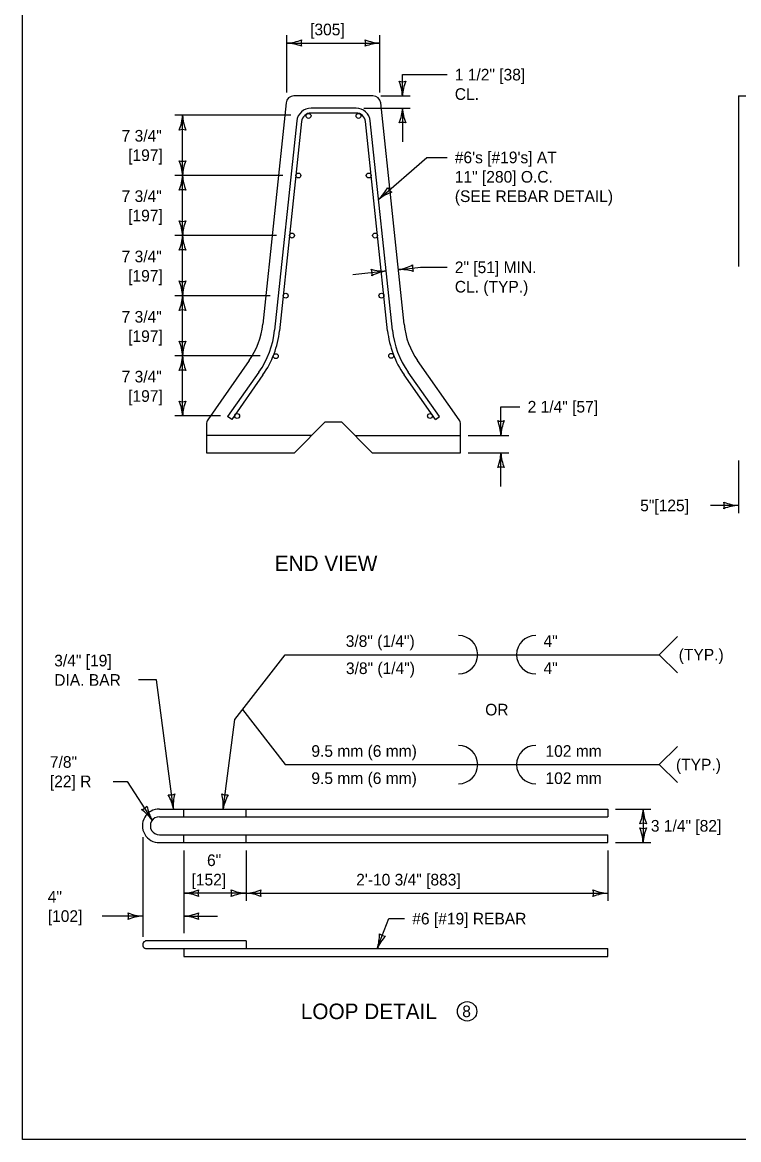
# Model space of a CAD drawing. Extents: x 49991.4 to 50021, y 49987.6 to 50011.4.
# Drawn here: x 49999.38 to 50003.08, y 49987.8 to 49993.56 of the extents above; entities that cross this region are included whole.
import ezdxf

# ---------------------------------------------------------------- set-up
doc = ezdxf.new("R2010")
doc.units = 0
for name, color, linetype in [('Level 1', 7, 'Continuous'), ('Level 2', 7, 'Continuous'), ('Level 3', 7, 'Continuous'), ('Level 4', 7, 'Continuous')]:
    doc.layers.add(name, color=color, linetype=linetype)

msp = doc.modelspace()

# ---------------------------------------------------------------- linework, layer by layer
at = {"layer": 'Level 1'}
for p, q in [((50001.1913, 49993.1797), (50000.7833, 49993.1797)), ((50003.0765, 49993.1796), (50007.8063, 49993.1796)), ((50003.0765, 49993.1796), (50003.0766, 49992.2998)), ((50000.7435, 49993.1439), (50000.6231, 49992.0024)), ((50001.1038, 49993.1169), (50000.8721, 49993.1169)), ((50001.3515, 49992.0024), (50001.2311, 49993.1439)), ((50000.7983, 49993.0507), (50000.6842, 49991.972)), ((50000.8235, 49993.0481), (50000.7094, 49991.9694)), ((50001.1038, 49993.0918), (50000.8721, 49993.0918)), ((50001.2666, 49991.9694), (50001.1525, 49993.0481)), ((50001.2917, 49991.972), (50001.1776, 49993.0507)), ((50000.553, 49991.815), (50000.3395, 49991.51)), ((50001.6351, 49991.51), (50001.4216, 49991.815)), ((50000.6032, 49991.7559), (50000.442, 49991.5263)), ((50000.6239, 49991.7415), (50000.4627, 49991.5118)), ((50001.5133, 49991.5118), (50001.3521, 49991.7415)), ((50001.534, 49991.5263), (50001.3728, 49991.7559)), ((50000.3323, 49991.4871), (50000.3323, 49991.3397)), ((50000.4627, 49991.5118), (50000.442, 49991.5263)), ((50000.9448, 49991.4997), (50000.7873, 49991.3397)), ((50000.9448, 49991.4997), (50001.0298, 49991.4997)), ((50001.0298, 49991.4997), (50001.1873, 49991.3397)), ((50001.5133, 49991.5118), (50001.534, 49991.5263)), ((50001.6423, 49991.3397), (50001.6423, 49991.4871)), ((50000.3323, 49991.3397), (50000.7873, 49991.3397)), ((50001.1873, 49991.3397), (50001.6423, 49991.3397)), ((50000.0909, 49989.5035), (50002.4015, 49989.5035)), ((50000.5367, 49989.4634), (50000.5367, 49989.5035)), ((50002.4015, 49989.5035), (50002.4015, 49989.4634)), ((50000.0908, 49989.4634), (50002.4015, 49989.4634)), ((50000.0908, 49989.3705), (50002.4015, 49989.3705)), ((50000.5367, 49989.3303), (50000.5367, 49989.3705)), ((50002.4015, 49989.3303), (50002.4015, 49989.3705)), ((50000.0908, 49989.3303), (50000.5367, 49989.3303)), ((50000.2156, 49989.3303), (50002.4015, 49989.3303)), ((50000.2156, 49989.3303), (50000.2156, 49989.3303)), ((50000.5367, 49989.3303), (50000.5367, 49989.3303)), ((50002.4015, 49989.3303), (50002.4015, 49989.3303)), ((50000.5367, 49988.8237), (50000.0243, 49988.8237)), ((50000.0243, 49988.7836), (50002.4015, 49988.7836)), ((50000.2156, 49988.7836), (50000.2156, 49988.7435)), ((50000.5367, 49988.8237), (50000.5367, 49988.7836)), ((50002.4015, 49988.7435), (50002.4015, 49988.7836)), ((50000.2156, 49988.7435), (50002.4015, 49988.7435))]:
    msp.add_line(p, q, dxfattribs=at)
msp.add_lwpolyline([(49999.3835, 49998.9992), (50016.7501, 49998.9992), (50016.7501, 49987.7988), (49999.3835, 49987.7988)], close=True, dxfattribs=at)
for centre, radius, start, end in [((50000.089, 49989.4169), 0.0866, 88.75473, 271.19725), ((50000.0899, 49989.417), 0.0465, 88.88791, 271.11208), ((50000.0243, 49988.8037), 0.0201, 89.93569, 270.06431)]:
    msp.add_arc(centre, radius, start, end, dxfattribs=at)
for centre, major_axis, ratio, start_param, end_param in [((50000.7833, 49993.1397), (-0.04, 0), 0.999982, 4.712389, 6.178105), ((50001.1913, 49993.1397), (-0.04, 0), 0.999982, 3.246673, 4.712389), ((50000.8721, 49993.0429), (-0.0742, 0), 0.997211, 4.712389, 6.178105), ((50001.1038, 49993.0429), (0.0742, 0), 0.997211, 0.10508, 1.570796), ((50000.8721, 49993.0429), (-0.049, 0), 0.997211, 4.712389, 6.178105), ((50001.1038, 49993.0429), (-0.049, 0), 0.997211, 3.246673, 4.712389), ((50000.2253, 49992.0444), (0.4, 0), 0.999982, 5.672459, 6.178105), ((50000.2243, 49992.0204), (0.4625, 0), 0.997211, 5.672459, 6.178105), ((50000.2243, 49992.0204), (0.4877, 0), 0.997211, 5.672459, 6.178105), ((50001.7517, 49992.0204), (-0.4877, 0), 0.997211, 0.10508, 0.610726), ((50001.7517, 49992.0204), (-0.4625, 0), 0.997211, 0.10508, 0.610726), ((50001.7492, 49992.0444), (-0.4, 0), 0.999982, 0.10508, 0.610726), ((50000.3723, 49991.4871), (-0.04, 0), 0.999982, 5.672459, 6.283185), ((50001.6023, 49991.4871), (0.04, 0), 0.999982, 0, 0.610726)]:
    msp.add_ellipse(centre, major_axis=major_axis, ratio=ratio, start_param=start_param, end_param=end_param, dxfattribs=at)
for centre in [(50000.8592, 49993.0768), (50001.1167, 49993.0768), (50000.8067, 49992.7699), (50001.1693, 49992.7699), (50000.7739, 49992.4599), (50001.202, 49992.46), (50000.7411, 49992.1498), (50001.2348, 49992.15), (50000.6901, 49991.8381), (50001.2852, 49991.8399), (50000.4907, 49991.5299), (50001.4852, 49991.5299)]:
    msp.add_ellipse(centre, major_axis=(0.0126, 0), ratio=0.999982, dxfattribs=at)
at = {"layer": 'Level 2'}
msp.add_circle((50001.6766, 49988.4603), 0.05, dxfattribs=at)
at = {"layer": 'Level 3'}
for p, q in [((50000.7473, 49993.1971), (50000.7473, 49993.4925)), ((50000.7473, 49993.4525), (50001.2273, 49993.4525)), ((50001.2273, 49993.1971), (50001.2273, 49993.4925)), ((50001.3432, 49993.1797), (50001.3432, 49993.2896)), ((50001.3432, 49993.2896), (50001.5731, 49993.2896)), ((50001.2313, 49993.1797), (50001.3832, 49993.1797)), ((50001.1438, 49993.1169), (50001.3832, 49993.1169)), ((50001.3432, 49993.1169), (50001.3432, 49992.9435)), ((50000.7679, 49993.0799), (50000.1695, 49993.0799)), ((50000.2095, 49992.7689), (50000.2095, 49993.0799)), ((50001.2205, 49992.6459), (50001.469, 49992.8629)), ((50001.469, 49992.8629), (50001.5731, 49992.8629)), ((50000.7267, 49992.7699), (50000.1695, 49992.7699)), ((50000.2095, 49992.4578), (50000.2095, 49992.7689)), ((50000.6939, 49992.4599), (50000.1695, 49992.4599)), ((50000.2095, 49992.1468), (50000.2095, 49992.4578)), ((50001.3217, 49992.2841), (50001.4371, 49992.2963)), ((50001.4371, 49992.2963), (50001.5731, 49992.2963)), ((50001.0869, 49992.2594), (50001.2594, 49992.2776)), ((50000.6611, 49992.1498), (50000.1695, 49992.1499)), ((50000.2095, 49991.8357), (50000.2095, 49992.1468)), ((50000.61, 49991.8399), (50000.1695, 49991.8399)), ((50000.2095, 49991.5299), (50000.2095, 49991.8357)), ((50001.851, 49991.5774), (50001.9487, 49991.5774)), ((50001.851, 49991.4297), (50001.851, 49991.5774)), ((50000.4046, 49991.5299), (50000.1695, 49991.5299)), ((50001.6823, 49991.4297), (50001.891, 49991.4297)), ((50001.6823, 49991.3397), (50001.891, 49991.3397)), ((50001.851, 49991.1662), (50001.851, 49991.3397)), ((50003.0765, 49991.2997), (50003.0765, 49991.0287)), ((50003.0765, 49991.0687), (50002.9318, 49991.0687)), ((50002.6675, 49990.2992), (50002.7609, 49990.3926)), ((50000.4785, 49989.9647), (50000.7378, 49990.2992)), ((50000.7378, 49990.2992), (50002.6675, 49990.2992)), ((50002.6675, 49990.2992), (50002.7609, 49990.206)), ((50000.0755, 49990.1688), (49999.9828, 49990.1688)), ((50000.5182, 49990.0158), (50000.7378, 49989.7325)), ((50002.6671, 49989.7325), (50002.7605, 49989.8259)), ((50000.7378, 49989.7325), (50002.6671, 49989.7325)), ((50002.6671, 49989.7325), (50002.7605, 49989.6393)), ((49999.8522, 49989.6459), (49999.9233, 49989.6459)), ((49999.9233, 49989.6459), (50000.0531, 49989.4454)), ((50002.4415, 49989.5035), (50002.624, 49989.5035)), ((50002.584, 49989.5035), (50002.584, 49989.3303)), ((50000.0043, 49989.3588), (50000.0043, 49988.8437)), ((50002.4415, 49989.3303), (50002.624, 49989.3303)), ((50000.2156, 49989.2903), (50000.2156, 49988.8637)), ((50000.5367, 49989.2903), (50000.5367, 49989.0293)), ((50002.4014, 49989.2903), (50002.4014, 49989.0293)), ((50000.5367, 49989.0693), (50000.2156, 49989.0693)), ((50000.5367, 49989.0693), (50002.4014, 49989.0693)), ((50000.0043, 49988.9514), (49999.795, 49988.9514)), ((50000.2156, 49988.9514), (50000.3891, 49988.9514)), ((50001.2729, 49988.9383), (50001.3538, 49988.9383))]:
    msp.add_line(p, q, dxfattribs=at)
for points in [[(50000.1622, 49989.5035), (50000.0755, 49990.1688)], [(50000.4184, 49989.5035), (50000.4785, 49989.9647)], [(50001.2131, 49988.7836), (50001.2729, 49988.9383)]]:
    msp.add_lwpolyline(points, dxfattribs=at)
for centre, radius, start, end in [((50000.7358, 49993.6852), 0.233, 272.82731, 292.07716), ((50000.7381, 49993.2303), 0.2223, 67.45601, 87.63952), ((50000.8755, 49993.4525), 0.0548, 162.13882, 197.86118), ((50001.2364, 49993.6746), 0.2223, 247.45601, 267.63952), ((50001.0991, 49993.4525), 0.0548, 342.13882, 17.86118), ((50001.2388, 49993.2198), 0.233, 92.82731, 112.07716), ((50001.3432, 49993.3079), 0.0548, 252.13882, 287.86118), ((50001.1105, 49993.1682), 0.233, 2.82731, 22.07716), ((50001.5653, 49993.1705), 0.2223, 157.45601, 177.63952), ((50001.1211, 49993.1261), 0.2223, 337.45601, 357.63952), ((50001.5759, 49993.1284), 0.233, 182.82731, 202.07716), ((49999.9874, 49993.0891), 0.2223, 337.45601, 357.63952), ((50000.4422, 49993.0914), 0.233, 182.82731, 202.07716), ((50001.3432, 49992.9887), 0.0548, 72.13882, 107.86118), ((50000.2095, 49992.9517), 0.0548, 72.13882, 107.86118), ((50000.2095, 49992.8981), 0.0548, 252.13882, 287.86118), ((49999.9768, 49992.7584), 0.233, 2.82731, 22.07716), ((50000.4316, 49992.7608), 0.2223, 157.45601, 177.63952), ((49999.9874, 49992.7791), 0.2223, 337.45601, 357.63952), ((50000.4422, 49992.7814), 0.233, 182.82731, 202.07716), ((50000.2095, 49992.6417), 0.0548, 72.13882, 107.86118), ((50001.0587, 49992.8136), 0.233, 313.95136, 333.20121), ((50001.317, 49992.7302), 0.0548, 203.26286, 238.98523), ((50001.3597, 49992.4725), 0.2223, 108.58006, 128.76356), ((50000.2095, 49992.5881), 0.0548, 252.13882, 287.86118), ((49999.9768, 49992.4484), 0.233, 2.82731, 22.07716), ((50000.4316, 49992.4508), 0.2223, 157.45601, 177.63952), ((49999.9874, 49992.4691), 0.2223, 337.45601, 357.63952), ((50000.4422, 49992.4714), 0.233, 182.82731, 202.07716), ((50000.2095, 49992.3317), 0.0548, 72.13882, 107.86118), ((50001.2859, 49992.5144), 0.233, 278.84787, 298.09772), ((50001.4492, 49992.2976), 0.0548, 168.15938, 203.88174), ((50001.2452, 49992.4994), 0.2223, 253.47657, 273.66008), ((50001.1319, 49992.2641), 0.0548, 348.15938, 23.88174), ((50001.2952, 49992.0473), 0.233, 98.84787, 118.09772), ((50001.3359, 49992.0623), 0.2223, 73.47657, 93.66008), ((50000.2095, 49992.2781), 0.0548, 252.13882, 287.86118), ((49999.9768, 49992.1384), 0.233, 2.82731, 22.07716), ((50000.4316, 49992.1408), 0.2223, 157.45601, 177.63952), ((49999.9874, 49992.1591), 0.2223, 337.45601, 357.63952), ((50000.4422, 49992.1614), 0.233, 182.82731, 202.07716), ((50000.2095, 49992.0217), 0.0548, 72.13882, 107.86118), ((50000.2095, 49991.9681), 0.0548, 252.13882, 287.86118), ((49999.9768, 49991.8284), 0.233, 2.82731, 22.07716), ((50000.4316, 49991.8308), 0.2223, 157.45601, 177.63952), ((49999.9874, 49991.8491), 0.2223, 337.45601, 357.63952), ((50000.4422, 49991.8514), 0.233, 182.82731, 202.07716), ((50000.2095, 49991.7117), 0.0548, 72.13882, 107.86118), ((50000.2095, 49991.6581), 0.0548, 252.13882, 287.86118), ((49999.9768, 49991.5184), 0.233, 2.82731, 22.07716), ((50000.4316, 49991.5208), 0.2223, 157.45601, 177.63952), ((50001.851, 49991.5579), 0.0548, 252.13882, 287.86118), ((50001.6183, 49991.4182), 0.233, 2.82731, 22.07716), ((50002.0731, 49991.4205), 0.2223, 157.45601, 177.63952), ((50001.6289, 49991.3488), 0.2223, 337.45601, 357.63952), ((50002.0837, 49991.3512), 0.233, 182.82731, 202.07716), ((50001.851, 49991.2115), 0.0548, 72.13882, 107.86118), ((50003.0857, 49991.2909), 0.2223, 247.45601, 267.63952), ((50002.9483, 49991.0687), 0.0548, 342.13882, 17.86118), ((50003.088, 49990.836), 0.233, 92.82731, 112.07716), ((50001.6323, 49990.2991), 0.0989, 270, 90), ((50002.0301, 49990.2991), 0.0989, 90, 270), ((50001.6323, 49989.7324), 0.0989, 270, 90), ((50002.0301, 49989.7324), 0.0989, 90, 270), ((50000.1456, 49989.6307), 0.0548, 259.56732, 295.28968), ((49999.9431, 49989.4657), 0.2223, 9.78898, 29.97249), ((50000.3945, 49989.5222), 0.233, 165.35134, 184.60119), ((50000.435, 49989.6307), 0.0548, 244.71032, 280.43268), ((50000.1862, 49989.5222), 0.233, 355.39881, 14.64866), ((50000.6375, 49989.4657), 0.2223, 150.02751, 170.21102), ((49999.9835, 49989.553), 0.0548, 285.05282, 320.77518), ((49999.864, 49989.3093), 0.233, 35.74131, 54.99116), ((50000.2446, 49989.5584), 0.2223, 190.37001, 210.55352), ((50002.3619, 49989.5127), 0.2223, 337.45601, 357.63952), ((50002.8167, 49989.515), 0.233, 182.82731, 202.07716), ((50002.584, 49989.3753), 0.0548, 72.13882, 107.86118), ((50002.584, 49989.4585), 0.0548, 252.13882, 287.86118), ((50002.3513, 49989.3188), 0.233, 2.82731, 22.07716), ((50002.8062, 49989.3212), 0.2223, 157.45601, 177.63952), ((50000.2041, 49989.3021), 0.233, 272.82731, 292.07716), ((50000.2065, 49988.8472), 0.2223, 67.45601, 87.63952), ((50000.3438, 49989.0693), 0.0548, 162.13882, 197.86118), ((50000.5458, 49989.2915), 0.2223, 247.45601, 267.63952), ((50000.4084, 49989.0693), 0.0548, 342.13882, 17.86118), ((50000.5481, 49988.8366), 0.233, 92.82731, 112.07716), ((50000.5252, 49989.3021), 0.233, 272.82731, 292.07716), ((50000.5275, 49988.8472), 0.2223, 67.45601, 87.63952), ((50000.6649, 49989.0693), 0.0548, 162.13882, 197.86118), ((50002.4106, 49989.2915), 0.2223, 247.45601, 267.63952), ((50002.2732, 49989.0693), 0.0548, 342.13882, 17.86118), ((50002.4129, 49988.8366), 0.233, 92.82731, 112.07716), ((50000.0135, 49989.1735), 0.2223, 247.45601, 267.63952), ((49999.8761, 49988.9514), 0.0548, 342.13882, 17.86118), ((50000.2041, 49989.1841), 0.233, 272.82731, 292.07716), ((50000.3438, 49988.9514), 0.0548, 162.13882, 197.86118), ((50000.0158, 49988.7186), 0.233, 92.82731, 112.07716), ((50000.2065, 49988.7292), 0.2223, 67.45601, 87.63952), ((50000.9919, 49988.8566), 0.233, 341.72472, 0.97457), ((50001.4171, 49988.6951), 0.2223, 136.35342, 156.53693), ((50001.2593, 49988.9032), 0.0548, 231.03623, 266.75859)]:
    msp.add_arc(centre, radius, start, end, dxfattribs=at)
at = {"layer": 'Level 4'}
for p, q in [((50000.8759, 49991.4297), (50000.3323, 49991.4297)), ((50001.0987, 49991.4297), (50001.6423, 49991.4297)), ((50000.2156, 49989.4634), (50000.2156, 49989.5035)), ((50000.2156, 49989.3303), (50000.2156, 49989.3705))]:
    msp.add_line(p, q, dxfattribs=at)

# ---------------------------------------------------------------- texts
at = {"layer": 'Level 2'}
for s, height, p in [('[305]', 0.06, (50000.8671, 49993.4925)), ('1 1/2" [38]', 0.06, (50001.6131, 49993.2596)), ('CL. ', 0.06, (50001.6131, 49993.1596)), ('7 3/4"', 0.06, (49999.8954, 49992.9444)), ('[197]', 0.06, (49999.9291, 49992.8444)), ("#6's [#19's] AT", 0.06, (50001.6131, 49992.8329)), ('11" [280] O.C.', 0.06, (50001.6131, 49992.7329)), ('7 3/4"', 0.06, (49999.8954, 49992.6333)), ('(SEE REBAR DETAIL)', 0.06, (50001.6131, 49992.6329)), ('[197]', 0.06, (49999.9291, 49992.5333)), ('7 3/4"', 0.06, (49999.8954, 49992.3223)), ('2" [51] MIN.', 0.06, (50001.6131, 49992.2663)), ('[197]', 0.06, (49999.9291, 49992.2223)), ('CL. (TYP.)', 0.06, (50001.6131, 49992.1663)), ('7 3/4"', 0.06, (49999.8954, 49992.0112)), ('[197]', 0.06, (49999.9291, 49991.9112)), ('7 3/4"', 0.06, (49999.8954, 49991.7028)), ('[197]', 0.06, (49999.9291, 49991.6028)), ('2 1/4" [57]', 0.06, (50001.9887, 49991.5474)), ('5"[125]', 0.06, (50002.5689, 49991.0387)), ('END VIEW', 0.08, (50000.6849, 49990.7303)), ('3/8" (1/4")', 0.06, (50001.0507, 49990.3392)), ('4"', 0.06, (50002.0703, 49990.3392)), ('(TYP.)', 0.06, (50002.7675, 49990.2692)), ('3/8" (1/4")', 0.06, (50001.0518, 49990.1991)), ('4"', 0.06, (50002.0703, 49990.1992)), ('OR', 0.06, (50001.7697, 49989.9858)), ('9.5 mm (6 mm)', 0.06, (50000.8736, 49989.7725)), ('102 mm', 0.06, (50002.0807, 49989.7725)), ('7/8"', 0.06, (49999.5256, 49989.7159)), ('(TYP.)', 0.06, (50002.7534, 49989.7023)), ('[22] R', 0.06, (49999.5256, 49989.6159)), ('9.5 mm (6 mm)', 0.06, (50000.8736, 49989.6325)), ('102 mm', 0.06, (50002.0807, 49989.6325)), ('3 1/4" [82]', 0.06, (50002.624, 49989.3869)), ('6"', 0.06, (50000.3356, 49989.2093)), ('[152]', 0.06, (50000.2558, 49989.1093)), ('2\'-10 3/4" [883]', 0.06, (50001.1047, 49989.1093)), ('4"', 0.06, (49999.5146, 49989.0214)), ('[102]', 0.06, (49999.5146, 49988.9214)), ('#6 [#19] REBAR', 0.06, (50001.3938, 49988.9083)), ('LOOP DETAIL', 0.08, (50000.8192, 49988.4203)), ('8', 0.06, (50001.6516, 49988.4303))]:
    msp.add_text(s, height=height, dxfattribs=at).set_placement(p)
for s, p in [('3/4" [19]', (49999.5479, 49990.2388)), ('DIA. BAR', (49999.5479, 49990.1388))]:
    msp.add_text(s, height=0.06, rotation=360, dxfattribs=at).set_placement(p)

doc.saveas('drawing.dxf')
